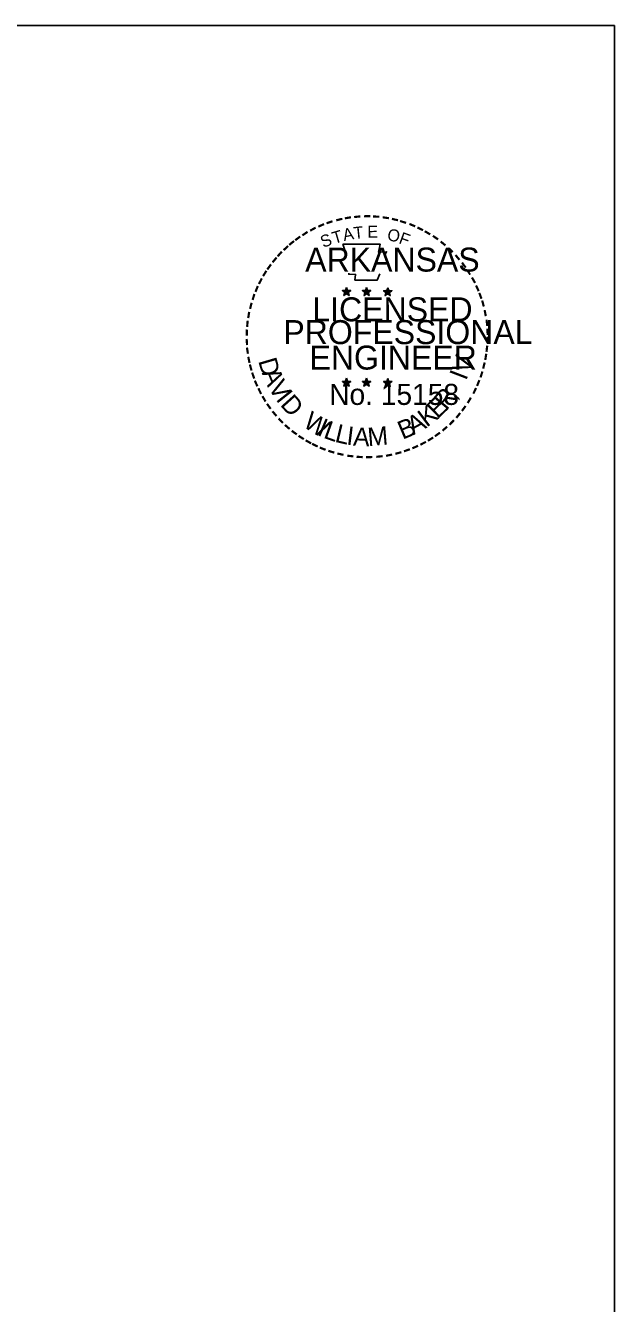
# Model space of a CAD drawing. Extents: x 96 to 721, y -177 to -41.
# Drawn here: x 660.1 to 685.4, y -95.6 to -40.6 of the extents above; entities that cross this region are included whole.
import ezdxf

# ---------------------------------------------------------------- set-up
doc = ezdxf.new("R2010")
doc.units = 0
doc.layers.add('R_Border', color=7, linetype='Continuous')
doc.layers.add('R_Border PE', color=7, linetype='Continuous')

msp = doc.modelspace()

# ---------------------------------------------------------------- linework, layer by layer
at = {"layer": 'R_Border'}
for points in [[(515.406, -40.582), (685.406, -40.582), (685.406, -150.582), (515.406, -150.582)], [(515.406, -40.582), (515.406, -150.582), (685.406, -150.582), (685.406, -40.582)]]:
    msp.add_lwpolyline(points, close=True, dxfattribs=at)
at = {"layer": 'R_Border PE'}
for p, q in [((673.694, -51.99), (673.874, -52.048)), ((673.694, -51.99), (673.824, -52.013)), ((673.694, -51.99), (673.816, -52.053)), ((673.762, -52.201), (673.874, -52.048)), ((673.762, -52.201), (673.827, -52.075)), ((673.762, -52.201), (673.873, -52.089)), ((673.874, -51.859), (673.853, -51.989)), ((673.984, -52.201), (673.873, -52.09)), ((673.874, -52.048), (673.874, -51.859)), ((673.874, -51.859), (673.899, -51.988)), ((674.053, -51.99), (673.874, -52.048)), ((673.984, -52.201), (673.874, -52.048)), ((674.053, -51.99), (673.905, -52.016)), ((673.984, -52.201), (673.913, -52.051)), ((674.053, -51.99), (673.948, -52.043)), ((674.555, -51.99), (674.735, -52.048)), ((674.555, -51.99), (674.685, -52.013)), ((674.555, -51.99), (674.677, -52.053)), ((674.624, -52.201), (674.735, -52.048)), ((674.624, -52.201), (674.689, -52.075)), ((674.624, -52.201), (674.734, -52.089)), ((674.735, -51.859), (674.714, -51.989)), ((674.845, -52.201), (674.734, -52.09)), ((674.735, -52.048), (674.735, -51.859)), ((674.735, -51.859), (674.76, -51.988)), ((674.914, -51.99), (674.735, -52.048)), ((674.845, -52.201), (674.735, -52.048)), ((674.914, -51.99), (674.766, -52.016)), ((674.845, -52.201), (674.774, -52.051)), ((674.914, -51.99), (674.809, -52.043)), ((675.465, -51.996), (675.645, -52.054)), ((675.465, -51.996), (675.595, -52.02)), ((675.465, -51.996), (675.587, -52.059)), ((675.533, -52.207), (675.645, -52.054)), ((675.533, -52.207), (675.598, -52.081)), ((675.533, -52.207), (675.643, -52.095)), ((675.645, -51.866), (675.623, -51.995)), ((675.754, -52.207), (675.643, -52.097)), ((675.645, -52.054), (675.645, -51.866)), ((675.645, -51.866), (675.67, -51.994)), ((675.823, -51.996), (675.645, -52.054)), ((675.754, -52.207), (675.645, -52.054)), ((675.823, -51.996), (675.676, -52.022)), ((675.754, -52.207), (675.684, -52.057)), ((675.823, -51.996), (675.718, -52.049)), ((673.692, -55.895), (673.872, -55.952)), ((673.692, -55.895), (673.822, -55.918)), ((673.692, -55.895), (673.814, -55.958)), ((673.76, -56.105), (673.872, -55.952)), ((673.76, -56.105), (673.825, -55.98)), ((673.76, -56.105), (673.871, -55.994)), ((673.872, -55.764), (673.851, -55.894)), ((673.982, -56.105), (673.871, -55.995)), ((673.872, -55.952), (673.872, -55.764)), ((673.872, -55.764), (673.897, -55.893)), ((674.051, -55.895), (673.872, -55.952)), ((673.982, -56.105), (673.872, -55.952)), ((674.051, -55.895), (673.903, -55.92)), ((673.982, -56.105), (673.911, -55.955)), ((674.051, -55.895), (673.946, -55.948)), ((674.552, -55.895), (674.732, -55.952)), ((674.552, -55.895), (674.683, -55.918)), ((674.552, -55.895), (674.675, -55.958)), ((674.621, -56.105), (674.732, -55.952)), ((674.621, -56.105), (674.686, -55.98)), ((674.621, -56.105), (674.731, -55.994)), ((674.732, -55.764), (674.711, -55.894)), ((674.842, -56.105), (674.731, -55.995)), ((674.732, -55.952), (674.732, -55.764)), ((674.732, -55.764), (674.758, -55.893)), ((674.911, -55.895), (674.732, -55.952)), ((674.842, -56.105), (674.732, -55.952)), ((674.911, -55.895), (674.764, -55.92)), ((674.842, -56.105), (674.772, -55.955)), ((674.911, -55.895), (674.806, -55.948)), ((675.464, -55.9), (675.643, -55.958)), ((675.464, -55.9), (675.594, -55.923)), ((675.464, -55.9), (675.586, -55.963)), ((675.532, -56.111), (675.643, -55.958)), ((675.532, -56.111), (675.597, -55.985)), ((675.532, -56.111), (675.642, -55.999)), ((675.643, -55.769), (675.622, -55.899)), ((675.753, -56.111), (675.642, -56)), ((675.643, -55.958), (675.643, -55.769)), ((675.643, -55.769), (675.669, -55.898)), ((675.822, -55.9), (675.643, -55.958)), ((675.753, -56.111), (675.643, -55.958)), ((675.822, -55.9), (675.675, -55.926)), ((675.753, -56.111), (675.683, -55.961)), ((675.822, -55.9), (675.717, -55.953))]:
    msp.add_line(p, q, dxfattribs=at)
for points in [[(673.715, -49.991), (673.854, -50.417)], [(675.525, -50.466), (675.599, -50.32), (675.245, -50.332), (675.322, -49.991), (673.715, -49.991)], [(673.969, -51.24), (673.969, -51.285), (674.259, -51.295), (674.231, -51.539), (675.195, -51.539), (675.299, -51.262)], [(673.874, -51.859), (673.984, -52.201), (673.694, -51.99), (674.053, -51.99), (673.762, -52.201), (673.874, -51.859)], [(674.735, -51.859), (674.845, -52.201), (674.555, -51.99), (674.914, -51.99), (674.624, -52.201), (674.735, -51.859)], [(675.645, -51.866), (675.754, -52.207), (675.465, -51.996), (675.823, -51.996), (675.533, -52.207), (675.645, -51.866)], [(673.872, -55.764), (673.982, -56.105), (673.692, -55.895), (674.051, -55.895), (673.76, -56.105), (673.872, -55.764)], [(674.732, -55.764), (674.842, -56.105), (674.552, -55.895), (674.911, -55.895), (674.621, -56.105), (674.732, -55.764)], [(675.643, -55.769), (675.753, -56.111), (675.464, -55.9), (675.822, -55.9), (675.532, -56.111), (675.643, -55.769)]]:
    msp.add_lwpolyline(points, dxfattribs=at)
for centre, radius in [((673.873, -52.048), 0.0888), ((673.873, -52.048), 0.0745), ((673.873, -52.048), 0.0597), ((673.873, -52.048), 0.0511), ((673.873, -52.048), 0.0385), ((673.873, -52.048), 0.0255), ((673.873, -52.048), 0.0153), ((674.734, -52.048), 0.0888), ((674.734, -52.048), 0.0745), ((674.734, -52.048), 0.0597), ((674.734, -52.048), 0.0511), ((674.734, -52.048), 0.0385), ((674.734, -52.048), 0.0255), ((674.734, -52.048), 0.0153), ((675.644, -52.054), 0.0888), ((675.644, -52.054), 0.0745), ((675.644, -52.054), 0.0597), ((675.644, -52.054), 0.0511), ((675.644, -52.054), 0.0385), ((675.644, -52.054), 0.0255), ((675.644, -52.054), 0.0153), ((673.871, -55.953), 0.0888), ((673.871, -55.953), 0.0745), ((673.871, -55.953), 0.0597), ((673.871, -55.953), 0.0511), ((673.871, -55.953), 0.0385), ((673.871, -55.953), 0.0255), ((673.871, -55.953), 0.0153), ((674.732, -55.953), 0.0888), ((674.732, -55.953), 0.0745), ((674.732, -55.953), 0.0597), ((674.732, -55.953), 0.0511), ((674.732, -55.953), 0.0385), ((674.732, -55.953), 0.0255), ((674.732, -55.953), 0.0153), ((675.643, -55.958), 0.0888), ((675.643, -55.958), 0.0745), ((675.643, -55.958), 0.0597), ((675.643, -55.958), 0.0511), ((675.643, -55.958), 0.0385), ((675.643, -55.958), 0.0255), ((675.643, -55.958), 0.0153)]:
    msp.add_circle(centre, radius, dxfattribs=at)

# ---------------------------------------------------------------- texts
for s, height, rotation, p in [('-', 0.825, 13.6302, (673.456, -49.285)), ('-', 0.825, 10.2193, (673.806, -49.202)), ('-', 0.825, 5.8968, (674.182, -49.145)), ('-', 0.825, 0.1862, (674.58, -49.108)), ('-', 0.825, 357.743, (674.952, -49.115)), ('-', 0.825, 352.1617, (675.336, -49.144)), ('-', 0.825, 347.2049, (675.707, -49.202)), ('-', 0.825, 342.3362, (676.034, -49.282)), ('-', 0.825, 34.0636, (672.108, -49.903)), ('-', 0.825, 28.7918, (672.416, -49.712)), ('-', 0.825, 24.3072, (672.742, -49.548)), ('-', 0.825, 19.1761, (673.069, -49.41)), ('T', 0.516, 16.4036, (673.338, -49.986)), ('A', 0.516, 11.2132, (673.764, -49.857)), ('T', 0.516, 6.0228, (674.202, -49.771)), ('E', 0.516, 0.8323, (674.771, -49.714)), ('O', 0.516, 350.4515, (675.599, -49.823)), ('F', 0.516, 340.0707, (676.09, -49.94)), ('-', 0.825, 337.8551, (676.413, -49.397)), ('-', 0.825, 334.1211, (676.739, -49.537)), ('-', 0.825, 329.6409, (677.037, -49.683)), ('-', 0.825, 42.9622, (671.342, -50.516)), ('-', 0.825, 38.9507, (671.565, -50.301)), ('-', 0.825, 36.2317, (671.81, -50.106)), ('S', 0.516, 21.594, (672.867, -50.157)), ('-', 0.825, 325.8627, (677.369, -49.869)), ('-', 0.825, 320.5297, (677.683, -50.089)), ('-', 0.825, 50.6142, (670.903, -51.013)), ('-', 0.825, 48.4231, (671.111, -50.763)), ('-', 0.825, 315.5786, (677.992, -50.34)), ('-', 0.825, 309.8797, (678.285, -50.624)), ('-', 0.825, 58.0706, (670.522, -51.577)), ('-', 0.825, 54.2325, (670.69, -51.306)), ('-', 0.825, 306.6522, (678.556, -50.934)), ('-', 0.722, 303.6753, (678.807, -51.227)), ('-', 0.825, 62.8713, (670.361, -51.894)), ('-', 0.825, 299.6684, (678.971, -51.54)), ('-', 0.825, 72.3945, (670.114, -52.534)), ('-', 0.825, 67.7743, (670.227, -52.209)), ('-', 0.825, 294.6628, (679.138, -51.856)), ('-', 0.825, 290.5728, (679.271, -52.153)), ('-', 0.825, 75.461, (670.013, -52.902)), ('-', 0.825, 285.1233, (679.391, -52.452)), ('-', 0.825, 85.1863, (669.905, -53.626)), ('-', 0.825, 81.2013, (669.945, -53.27)), ('-', 0.825, 280.5493, (679.495, -52.835)), ('-', 0.825, 276.5962, (679.578, -53.231)), ('-', 0.825, 89.0622, (669.893, -53.987)), ('-', 0.825, 274.3301, (679.609, -53.603)), ('-', 0.825, 94.1959, (669.911, -54.361)), ('-', 0.825, 98.9479, (669.948, -54.705)), ('-', 0.825, 263.5172, (679.617, -54.272)), ('-', 0.825, 269.9407, (679.627, -53.929)), ('-', 0.825, 101.7149, (670.017, -55.083)), ('D', 0.794, 286.2848, (670.063, -55.012)), ('V', 0.794, 72.6573, (679.134, -55.61)), ('-', 0.825, 260.9953, (679.58, -54.61)), ('-', 0.825, 105.4578, (670.101, -55.39)), ('-', 0.825, 109.0874, (670.212, -55.715)), ('A', 0.794, 292.7835, (670.214, -55.528)), ('I', 0.794, 69.0301, (679.02, -55.888)), ('-', 0.825, 252.8681, (679.43, -55.331)), ('-', 0.825, 255.7626, (679.523, -54.959)), ('-', 0.825, 114.0643, (670.343, -56.022)), ('V', 0.794, 300.7936, (670.479, -56.136)), ('-', 0.825, 247.8887, (679.315, -55.678)), ('-', 0.825, 115.7289, (670.5, -56.341)), ('-', 0.825, 120.4471, (670.684, -56.643)), ('I', 0.794, 308.3502, (670.804, -56.671)), ('D', 0.794, 311.9774, (670.985, -56.911)), ('E', 0.794, 44.0175, (677.79, -57.536)), ('R', 0.794, 50.3651, (678.169, -57.172)), (',', 0.794, 57.4684, (678.541, -56.717)), ('-', 0.825, 239.0712, (678.977, -56.39)), ('-', 0.825, 244.6197, (679.18, -56.002)), ('-', 0.825, 125.8934, (670.892, -56.933)), ('-', 0.825, 130.7181, (671.13, -57.217)), ('W', 0.794, 328.0731, (671.954, -57.822)), ('K', 0.794, 36.9143, (677.321, -57.892)), ('-', 0.825, 233.8452, (678.77, -56.726)), ('-', 0.825, 134.2238, (671.397, -57.498)), ('-', 0.825, 138.9338, (671.667, -57.737)), ('I', 0.794, 336.6877, (672.566, -58.188)), ('L', 0.794, 340.3149, (672.839, -58.314)), ('L', 0.794, 346.6625, (673.334, -58.491)), ('B', 0.794, 22.8589, (676.283, -58.413)), ('A', 0.794, 28.9042, (676.745, -58.221)), ('-', 0.825, 225.7653, (678.301, -57.309)), ('-', 0.825, 231.2538, (678.548, -57.018)), ('-', 0.825, 144.6463, (671.954, -57.947)), ('-', 0.825, 148.0898, (672.243, -58.138)), ('I', 0.794, 353.0101, (673.845, -58.613)), ('A', 0.794, 356.6373, (674.143, -58.657)), ('M', 0.794, 4.6473, (674.805, -58.687)), ('-', 0.825, 212.2491, (677.473, -58.014)), ('-', 0.825, 215.7363, (677.749, -57.815)), ('-', 0.825, 221.0851, (678.032, -57.571)), ('-', 0.825, 151.5704, (672.542, -58.306)), ('-', 0.825, 154.6002, (672.811, -58.433)), ('-', 0.825, 158.5612, (673.133, -58.564)), ('-', 0.825, 162.7983, (673.487, -58.674)), ('-', 0.825, 199.4643, (676.538, -58.5)), ('-', 0.825, 204.2516, (676.864, -58.357)), ('-', 0.825, 207.3568, (677.186, -58.193)), ('-', 0.825, 167.5555, (673.856, -58.758)), ('-', 0.825, 173.1155, (674.254, -58.815)), ('-', 0.825, 176.5183, (674.639, -58.842)), ('-', 0.825, 181.5918, (675.023, -58.833)), ('-', 0.825, 185.8167, (675.44, -58.793)), ('-', 0.825, 191.2858, (675.82, -58.725)), ('-', 0.825, 195.4743, (676.196, -58.623))]:
    msp.add_text(s, height=height, rotation=rotation, dxfattribs=at).set_placement(p)
for s, height, p in [('ARKANSAS', 1.0312, (672.092, -51.17)), ('LICENSED', 1.0312, (672.4, -53.31)), ('PROFESSIONAL', 1.03125, (671.151, -54.292)), ('ENGINEER', 1.0312, (672.278, -55.387)), ('No. 15158', 0.906, (673.125, -56.909)), ('AAMU', 0.0000103, (674.698, -58.69))]:
    msp.add_text(s, height=height, dxfattribs=at).set_placement(p)

doc.saveas('drawing.dxf')
